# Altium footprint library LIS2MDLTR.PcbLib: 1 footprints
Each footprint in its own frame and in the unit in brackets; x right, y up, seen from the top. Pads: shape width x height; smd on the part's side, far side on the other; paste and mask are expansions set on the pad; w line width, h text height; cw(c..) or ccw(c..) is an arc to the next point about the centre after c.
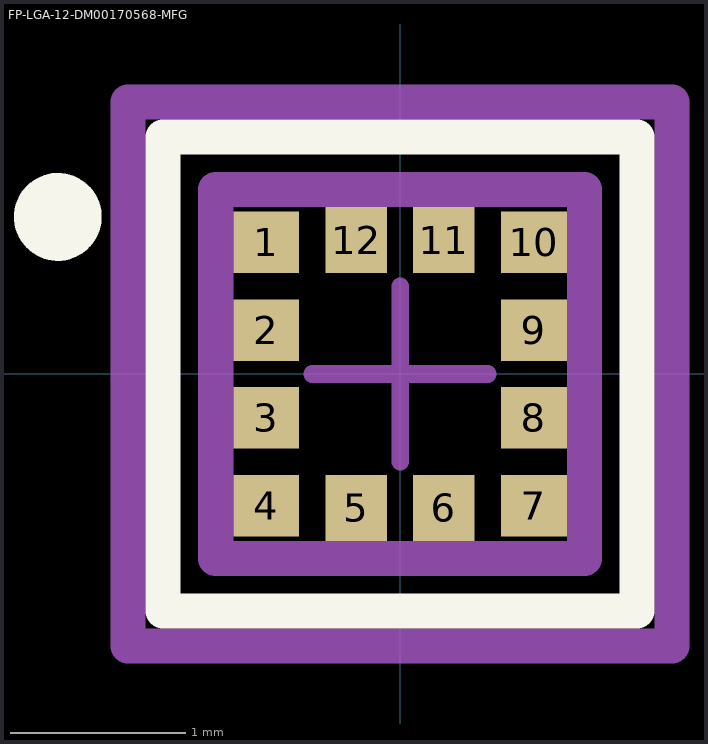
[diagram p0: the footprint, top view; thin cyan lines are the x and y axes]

## FP-LGA-12-DM00170568-MFG [mm]
pads (12):
  rect 0.375x0.35 smd paste+0 mask+0: 1(-0.763,0.75) 2(-0.763,0.25) 3(-0.763,-0.25) 4(-0.763,-0.75) 7(0.763,-0.75) 8(0.763,-0.25) 9(0.763,0.25) 10(0.763,0.75)
  rect 0.35x0.375 smd paste+0 mask+0: 5(-0.25,-0.763) 6(0.25,-0.763) 11(0.25,0.763) 12(-0.25,0.763)
Top Overlay:
  circle w0.25: c-1.95,0.895 r0.125
  lines w0.2: -1.35,-1.35 -1.35,1.35 1.35,1.35 1.35,-1.35 -1.35,-1.35
Top Assembly:
  lines w0.2: -1.55,-1.55 -1.55,1.55 1.55,1.55 1.55,-1.55 -1.55,-1.55
  text ".Designator" at 0,0.188 h1
Top 3D Body:
  lines w0.2: -1.05,-1.05 -1.05,1.05 1.05,1.05 1.05,-1.05 -1.05,-1.05
Top Courtyard:
  lines w0.2: -1.55,-1.55 -1.55,1.55 1.55,1.55 1.55,-1.55 -1.55,-1.55
Top Component Center:
  lines w0.1: -0.5,0 0.5,0 ; 0,-0.5 0,0.5
3D body "IC_STMicroelectronics_LIS2MDLTR_eec.STEP": height 0.25, standoff 0, extent -1.55,-1.55 1.55,1.55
